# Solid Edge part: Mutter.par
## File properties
Dokumentum tartalom típus: 0
Last saved by: psaghy
Revision: 77
Sűrűség: 0,000 kg/m^3
Pontosság: 0,990
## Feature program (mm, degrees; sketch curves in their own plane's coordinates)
base feature "unnamed BaseFeature 1"
sketch for "Furat_1" plane through (8, 0, 0) normal (1, 0, 0) x-axis (0, 0, 1)
hole "Furat_1" through  StartChamferOffset = 0.49 mm; StartChamferAngle = 45 deg
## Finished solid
Body 1: solid body, 23 faces, 47 edges, 26 vertices.
  Faces by surface: cone 14, plane 8, cylinder 1
  Edges by curve: spline 24, circle 16, line 7
Bounding box of the edges (mm): 8.000 x 27.713 x 24.000, from (0, -13.8564, -12) to (8, 13.8564, 12).
Cylindrical faces by radius (mm): R7.188 x1
Conical faces (half-angle, radius in mm at the cone's reference point): 45 deg R7.678 x1, 60 deg R7.5939 x1, 60 deg R12.9282 x12
Planar faces by outward normal: +x 1, +z 1, -x 1, -z 1, oblique 4
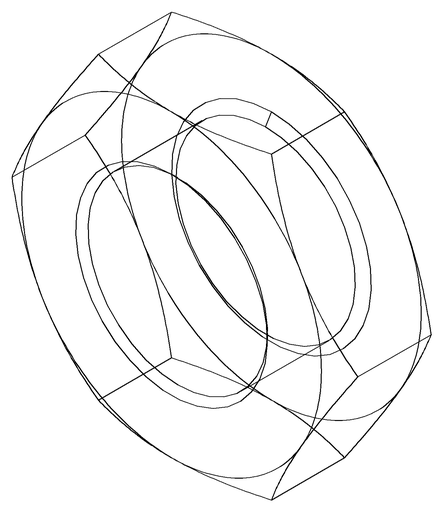
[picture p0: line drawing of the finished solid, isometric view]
